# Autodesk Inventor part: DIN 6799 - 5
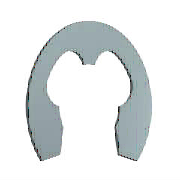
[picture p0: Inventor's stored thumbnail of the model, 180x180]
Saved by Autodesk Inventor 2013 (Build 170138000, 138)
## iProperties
Created: 2012-02
Part Number: DIN 6799 - 5
Material: Stahl, weich
Description: Sicherungsscheibe
Document SubType Name: Modeling
Standard: DIN 6799
Designer: rYan
Standards Organization: DIN
Language: de-DE
Size Designation: 5
Categories: <MemberInstance><Categories><Category DisplayName="Wellenteile" InternalName="7f7aeb1f-a693-4053-b835-cee3144e0d98" Mnemonic="SHFT"><Category DisplayName="Siche
Density: 7.86 g/cm^3
Mass: 0.268984 g
Surface Area: 1.34121 cm^2
Volume: 0.0342219 cm^3
IsCustomPart: 0
Author: rYan
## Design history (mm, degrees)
sketch "Skizze1"
  geometry: L1 (-0.5, 0.024)-(0, 0.024) reference; L2 (-3.206, 0)-(3.486, 0) reference; L3 (-2.291, -3.976)-(2.291, -3.976); L4 (0, 1.949)-(0, -3.479) reference; L5 (-3, -1.976)-(-2.51, -1.976); L6 (-0.5, 0.024)-(-0.5, 0.509); L7 (0, 2.674)-(2.53, 2.674); L8 (-2.291, -3.976)-(-3.095, -6.309); L9 (0, -0.476)-(-1.278, -0.476); L10 (2.291, -3.976)-(3.095, -6.309); L11 (3, -1.976)-(2.51, -1.976); L12 (0.5, 0.024)-(0.5, 0.509); C1 r 3 at (0, -2.976); A1 r 2.5 centre (0, -2.976) between (-2.368, -2.174) and (-2.291, -3.976); A2 r 0.5 centre (0, 0.024) between (-0.5, 0.024) and (0.5, 0.024); A3 r 5.65 centre (0, -2.976) between (4.386, -6.538) and (-4.386, -6.538); A4 r 4 centre (0, -2.976) between (-1, 0.897) and (-3.529, -1.094); A5 r 0.4 centre (-0.9, 0.509) between (-0.5, 0.509) and (-1, 0.897); A6 r 0.6 centre (-3, -1.376) between (-3.529, -1.094) and (-3, -1.976); A7 r 0.15 centre (-2.51, -2.126) between (-2.368, -2.174) and (-2.51, -1.976); A8 r 0.75 centre (-3.804, -6.065) between (-4.386, -6.538) and (-3.095, -6.309); A9 r 0.75 centre (3.804, -6.065) between (3.095, -6.309) and (4.386, -6.538); A10 r 2.5 centre (0, -2.976) between (2.291, -3.976) and (2.368, -2.174); A11 r 0.15 centre (2.51, -2.126) between (2.51, -1.976) and (2.368, -2.174); A12 r 0.6 centre (3, -1.376) between (3, -1.976) and (3.529, -1.094); A13 r 4 centre (0, -2.976) between (3.529, -1.094) and (1, 0.897); A14 r 0.4 centre (0.9, 0.509) between (1, 0.897) and (0.5, 0.509); 1 further point
  constraints: 30 point on circle, 20 end point, 15 centre point, 13 symmetric about line, 12 tangent, 8 point on line, 4 parallel, 2 coincident, 2 horizontal, 1 concentric, 1 perpendicular, 1 vertical alignment, 9 other
  dimensions: "d0" = 6 diameter of C1 (= WD); "d3" = 1 distance from line of A1.centre L3 (= 0.2 x ND); "d4" = 0.5 radius of A2 (= 0.1 x ND); "d5" = 11.3 diameter of A3 (= SD2); "d8" = 4 radius of A4 (= 0.8 x ND); "d9" = 1 distance from line of A1.centre L5 (= 0.2 x ND); "d10" = 0.4 radius of A5 (= 0.08 x ND); "d11" = 0.6 radius of A6 (= 0.12 x ND); "d12" = 0.15 radius of A7 (= 0.03 x ND); "d13" = 0.75 radius of A8 (= 0.15 x ND); "d14" = 2.5 distance from line of A1.centre L9 (= 0.5 x ND); "d15" = 2.5 radius of A1 (= 0.5 x ND)
extrude "Körper" new body sketch "Skizze1" distance "d16" = 0.7 (= SD); taper "d17" = 0 deg
workaxis "Work Axis1"
workaxis "Work Axis2"
workplane "Work Plane1"
body "Solid1"
other parameters: "ND" = 5 [user parameter; used in 14 equation terms], "SD" = 0.7 [user parameter; used in 1 equation term], "WD" = 6 [user parameter; used in 1 equation term], "d1" = 8 (= 1.6 x ND), "d2" = 5 (= ND), "SD2" = 11.3 [user parameter; used in 1 equation term], "d6" = 5 (= ND), "d7" = 0.75 (= 0.15 x ND), "d18" = 0, "d19" = 0, "d27" = 0, "d28" = 0, "WDMIN" = 5 [user parameter], "SNB" = 0.74 [user parameter], "WDMAX" = 7 [user parameter], "BUBRMI" = 1.2 [user parameter]
